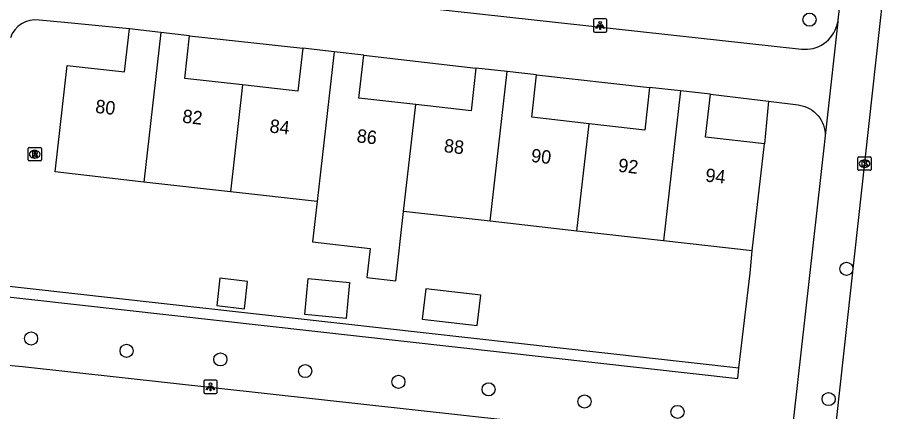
# Model space of a CAD drawing. Extents: x 161928 to 163055, y 386475 to 387428.
# Drawn here: x 162311.1 to 162376.1, y 386864.9 to 386894.3 of the extents above; entities that cross this region are included whole.
import ezdxf

# ---------------------------------------------------------------- set-up
doc = ezdxf.new("R2010")
doc.units = 0
for name, color, linetype in [('IMGEO_Boom', 7, 'Continuous'), ('IMGEO_Groenvoorziening', 7, 'Continuous'), ('IMGEO_Haag', 7, 'Continuous'), ('IMGEO_Kolk', 7, 'Continuous'), ('IMGEO_Lichtpunt', 7, 'Continuous'), ('IMGEO_Pand', 7, 'Continuous'), ('IMGEO_Pand_nummerreeks', 7, 'Continuous'), ('IMGEO_Rijbaan_lokaal_open', 7, 'Continuous'), ('IMGEO_Rioolput', 7, 'Continuous'), ('IMGEO_Voetpad_open', 7, 'Continuous')]:
    doc.layers.add(name, color=color, linetype=linetype)

msp = doc.modelspace()

# ---------------------------------------------------------------- linework, layer by layer
at = {"layer": 'IMGEO_Boom'}
for centre in [(162370.216, 386894.146), (162372.966, 386875.548), (162312.161, 386870.347), (162319.283, 386869.426), (162326.278, 386868.782), (162332.6, 386867.915), (162339.554, 386867.108), (162346.282, 386866.549), (162353.431, 386865.642), (162371.642, 386865.821), (162360.374, 386864.866)]:
    msp.add_circle(centre, 0.489, dxfattribs=at)
at = {"layer": 'IMGEO_Groenvoorziening'}
for points in [[(162367.146, 386888.052), (162366.851, 386884.866)], [(162364.954, 386868.146), (162365.792, 386875.232), (162365.946, 386876.882)]]:
    msp.add_lwpolyline(points, dxfattribs=at)
at = {"layer": 'IMGEO_Haag'}
for points in [[(162308.514, 386874.479), (162364.954, 386868.146)], [(162308.425, 386873.684), (162364.865, 386867.351), (162364.954, 386868.146)]]:
    msp.add_lwpolyline(points, dxfattribs=at)
at = {"layer": 'IMGEO_Kolk'}
for p, q in [((162373.822, 386882.974), (162373.822, 386883.826)), ((162373.897, 386883.9), (162374.749, 386883.9)), ((162374.31, 386883.68), (162374.335, 386883.68)), ((162374.823, 386883.826), (162374.823, 386882.974)), ((162374.749, 386882.9), (162373.897, 386882.9)), ((162374.333, 386883.12), (162374.308, 386883.12))]:
    msp.add_line(p, q, dxfattribs=at)
for points in [[(162373.822, 386882.974), (162373.822, 386883.826)], [(162373.897, 386883.9), (162374.749, 386883.9)], [(162374.143, 386883.6), (162374.266, 386883.6), (162374.266, 386883.449), (162374.396, 386883.6), (162374.56, 386883.6), (162374.414, 386883.449), (162374.567, 386883.2), (162374.415, 386883.2), (162374.33, 386883.364), (162374.266, 386883.297), (162374.266, 386883.2), (162374.143, 386883.2), (162374.143, 386883.6)], [(162374.823, 386883.826), (162374.823, 386882.974)], [(162374.749, 386882.9), (162373.897, 386882.9)]]:
    msp.add_lwpolyline(points, dxfattribs=at)
for centre, start, end in [((162373.899, 386883.824), 91.55205, 178.44795), ((162373.899, 386883.824), 91.55205, 178.44795), ((162374.747, 386883.824), 1.55205, 88.44795), ((162374.747, 386883.824), 1.55205, 88.44795), ((162373.899, 386882.976), 181.55205, 268.44795), ((162373.899, 386882.976), 181.55205, 268.44795), ((162374.747, 386882.976), 271.55205, 358.44795), ((162374.747, 386882.976), 271.55205, 358.44795)]:
    msp.add_arc(centre, 0.0765, start, end, dxfattribs=at)
for centre, major_axis, ratio, start_param, end_param in [((162374.309, 386883.4), (-0.387, 0.002), 0.722429, 4.712389, 7.853982), ((162374.334, 386883.4), (-0.39, 0.002), 0.717154, 1.570796, 4.712389)]:
    msp.add_ellipse(centre, major_axis=major_axis, ratio=ratio, start_param=start_param, end_param=end_param, dxfattribs=at)
at = {"layer": 'IMGEO_Lichtpunt'}
for p, q in [((162354.102, 386894.123), (162354.102, 386893.316)), ((162354.102, 386894.123), (162354.102, 386893.316)), ((162355.004, 386894.218), (162354.196, 386894.218)), ((162355.004, 386894.218), (162354.196, 386894.218)), ((162355.098, 386893.316), (162355.098, 386894.123)), ((162355.098, 386893.316), (162355.098, 386894.123)), ((162354.196, 386893.222), (162355.004, 386893.222)), ((162354.196, 386893.222), (162355.004, 386893.222)), ((162325.037, 386867.135), (162325.037, 386866.328)), ((162325.037, 386867.135), (162325.037, 386866.328)), ((162325.939, 386867.23), (162325.131, 386867.23)), ((162325.939, 386867.23), (162325.131, 386867.23)), ((162326.033, 386866.328), (162326.033, 386867.135)), ((162326.033, 386866.328), (162326.033, 386867.135)), ((162325.131, 386866.234), (162325.939, 386866.234)), ((162325.131, 386866.234), (162325.939, 386866.234))]:
    msp.add_line(p, q, dxfattribs=at)
for points in [[(162354.476, 386893.787), (162354.515, 386893.759), (162354.327, 386893.497), (162354.289, 386893.524), (162354.476, 386893.787)], [(162354.578, 386893.739), (162354.625, 386893.739), (162354.625, 386893.417), (162354.578, 386893.417), (162354.578, 386893.739)], [(162354.688, 386893.759), (162354.726, 386893.786), (162354.913, 386893.524), (162354.874, 386893.496), (162354.688, 386893.759)], [(162325.411, 386866.799), (162325.45, 386866.771), (162325.262, 386866.509), (162325.224, 386866.536), (162325.411, 386866.799)], [(162325.513, 386866.751), (162325.56, 386866.751), (162325.56, 386866.429), (162325.513, 386866.429), (162325.513, 386866.751)], [(162325.623, 386866.771), (162325.661, 386866.798), (162325.848, 386866.536), (162325.809, 386866.508), (162325.623, 386866.771)]]:
    msp.add_lwpolyline(points, dxfattribs=at)
for centre in [(162354.601, 386893.921), (162325.536, 386866.933)]:
    msp.add_circle(centre, 0.0994, dxfattribs=at)
for centre, start, end in [((162354.196, 386894.123), 90, 180), ((162354.196, 386894.123), 90, 180), ((162355.004, 386894.123), 0, 90), ((162355.004, 386894.123), 0, 90), ((162354.196, 386893.316), 180, 270), ((162354.196, 386893.316), 180, 270), ((162355.004, 386893.316), 270, 0), ((162355.004, 386893.316), 270, 360), ((162325.131, 386867.135), 90, 180), ((162325.131, 386867.135), 90, 180), ((162325.939, 386867.135), 0, 90), ((162325.939, 386867.135), 0, 90), ((162325.131, 386866.328), 180, 270), ((162325.131, 386866.328), 180, 270), ((162325.939, 386866.328), 270, 0), ((162325.939, 386866.328), 270, 360)]:
    msp.add_arc(centre, 0.0946, start, end, dxfattribs=at)
at = {"layer": 'IMGEO_Pand'}
for points in [[(162320.569, 386882.025), (162313.947, 386882.776), (162314.848, 386890.729), (162319.14, 386890.243), (162319.504, 386893.456)], [(162321.835, 386893.192), (162319.504, 386893.456)], [(162321.835, 386893.192), (162320.569, 386882.025)], [(162323.976, 386892.949), (162321.835, 386893.192)], [(162327.932, 386889.278), (162323.616, 386889.767), (162323.976, 386892.949)], [(162332.419, 386892.02), (162332.056, 386888.81), (162327.932, 386889.278)], [(162334.756, 386891.755), (162332.419, 386892.02)], [(162334.756, 386891.755), (162333.486, 386880.561)], [(162336.973, 386891.504), (162334.756, 386891.755)], [(162340.85, 386887.811), (162336.609, 386888.292), (162336.973, 386891.504)], [(162345.337, 386890.535), (162344.975, 386887.344), (162340.85, 386887.811)], [(162347.67, 386890.271), (162345.337, 386890.535)], [(162346.403, 386879.097), (162347.67, 386890.271)], [(162349.855, 386890.023), (162347.67, 386890.271)], [(162353.771, 386886.377), (162349.496, 386886.861), (162349.855, 386890.023)], [(162327.932, 386889.278), (162327.027, 386881.293)], [(162358.293, 386889.092), (162357.932, 386885.905), (162353.771, 386886.377)], [(162360.59, 386888.832), (162358.293, 386889.092)], [(162360.59, 386888.832), (162359.32, 386877.633)], [(162362.821, 386888.579), (162360.59, 386888.832)], [(162366.851, 386884.866), (162362.457, 386885.364), (162362.821, 386888.579)], [(162339.945, 386879.829), (162340.85, 386887.811)], [(162352.862, 386878.365), (162353.771, 386886.377)], [(162365.946, 386876.882), (162366.851, 386884.866)], [(162327.027, 386881.293), (162320.569, 386882.025)], [(162333.486, 386880.561), (162327.027, 386881.293)], [(162333.486, 386880.561), (162333.145, 386877.551), (162337.44, 386877.064), (162337.194, 386874.893), (162339.358, 386874.648), (162339.945, 386879.829)], [(162346.403, 386879.097), (162339.945, 386879.829)], [(162352.862, 386878.365), (162346.403, 386879.097)], [(162359.32, 386877.633), (162352.862, 386878.365)], [(162365.946, 386876.882), (162359.32, 386877.633)], [(162328.311, 386874.605), (162326.25, 386874.839), (162326.019, 386872.803), (162328.08, 386872.57), (162328.311, 386874.605)], [(162335.9, 386874.527), (162335.649, 386871.843), (162332.568, 386872.131), (162332.819, 386874.815), (162335.9, 386874.527)], [(162345.693, 386873.589), (162341.595, 386874.053), (162341.337, 386871.778), (162345.435, 386871.314), (162345.693, 386873.589)]]:
    msp.add_lwpolyline(points, dxfattribs=at)
at = {"layer": 'IMGEO_Rijbaan_lokaal_open'}
msp.add_lwpolyline([(162371.672, 386859.36), (162371.777, 386860.229), (162372.249, 386864.452), (162381.298, 386946.838), (162381.805, 386950.758), (162381.864, 386951.24)], dxfattribs=at)
at = {"layer": 'IMGEO_Rioolput'}
for p, q in [((162312.01, 386884.6), (162312.862, 386884.6)), ((162311.935, 386883.674), (162311.935, 386884.526)), ((162312.423, 386884.38), (162312.448, 386884.38)), ((162312.936, 386884.526), (162312.936, 386883.674)), ((162312.862, 386883.6), (162312.01, 386883.6)), ((162312.446, 386883.82), (162312.421, 386883.82))]:
    msp.add_line(p, q, dxfattribs=at)
for points in [[(162312.01, 386884.6), (162312.862, 386884.6)], [(162311.935, 386883.674), (162311.935, 386884.526)], [(162312.524, 386884.298), (162312.272, 386884.3), (162312.272, 386883.9)], [(162312.272, 386883.9), (162312.396, 386883.9), (162312.396, 386884.062), (162312.407, 386884.062)], [(162312.45, 386884.219), (162312.396, 386884.219), (162312.396, 386884.138)], [(162312.396, 386884.138), (162312.448, 386884.138)], [(162312.454, 386884.033), (162312.525, 386883.9), (162312.665, 386883.9), (162312.6, 386884.026)], [(162312.936, 386884.526), (162312.936, 386883.674)], [(162312.862, 386883.6), (162312.01, 386883.6)]]:
    msp.add_lwpolyline(points, dxfattribs=at)
for centre, radius, start, end in [((162312.012, 386884.524), 0.0765, 91.55205, 178.44795), ((162312.012, 386884.524), 0.0765, 91.55205, 178.44795), ((162312.86, 386884.524), 0.0765, 1.55205, 88.44795), ((162312.86, 386884.524), 0.0765, 1.55205, 88.44795), ((162312.406, 386884.009), 0.0533, 26.02933, 88.69889), ((162312.432, 386884.327), 0.19, 274.7715, 282.96867), ((162312.456, 386884.123), 0.0964, 77.00612, 93.18647), ((162312.47, 386884.18), 0.0378, 276.66336, 79.67722), ((162312.523, 386884.188), 0.109, 350.36119, 89.41601), ((162312.521, 386884.188), 0.112, 277.58423, 350.98172), ((162312.505, 386883.973), 0.108, 29.51342, 73.79051), ((162312.012, 386883.676), 0.0765, 181.55205, 268.44795), ((162312.012, 386883.676), 0.0765, 181.55205, 268.44795), ((162312.86, 386883.676), 0.0765, 271.55205, 358.44795), ((162312.86, 386883.676), 0.0765, 271.55205, 358.44795)]:
    msp.add_arc(centre, radius, start, end, dxfattribs=at)
for centre, major_axis, ratio, start_param, end_param in [((162312.422, 386884.1), (-0.387, 0.002), 0.722429, 4.712389, 7.853982), ((162312.447, 386884.1), (-0.39, 0.002), 0.717154, 1.570796, 4.712389)]:
    msp.add_ellipse(centre, major_axis=major_axis, ratio=ratio, start_param=start_param, end_param=end_param, dxfattribs=at)
at = {"layer": 'IMGEO_Voetpad_open'}
for points in [[(162374.683, 386914.918), (162372.335, 386894.112), (162372.318, 386893.989)], [(162313.257, 386898.144), (162315.471, 386897.91), (162369.622, 386891.948), (162369.841, 386891.933), (162370.06, 386891.938), (162370.278, 386891.962), (162370.493, 386892.006), (162370.703, 386892.069), (162370.907, 386892.15), (162371.103, 386892.249), (162371.289, 386892.365), (162371.464, 386892.498), (162371.626, 386892.645), (162371.775, 386892.807), (162371.908, 386892.981), (162372.026, 386893.166), (162372.126, 386893.361), (162372.209, 386893.564), (162372.273, 386893.774), (162372.318, 386893.989)], [(162319.504, 386893.456), (162314.661, 386893.924), (162312.752, 386894.12)], [(162372.318, 386893.989), (162371.364, 386885.262)], [(162323.976, 386892.949), (162332.419, 386892.02)], [(162336.973, 386891.504), (162345.337, 386890.535)], [(162349.855, 386890.023), (162358.293, 386889.092)], [(162362.821, 386888.579), (162367.146, 386888.052)], [(162367.146, 386888.052), (162369.374, 386887.78), (162369.465, 386887.767), (162369.664, 386887.725), (162369.859, 386887.666), (162370.048, 386887.589), (162370.23, 386887.496), (162370.402, 386887.387), (162370.564, 386887.263), (162370.714, 386887.125), (162370.851, 386886.974), (162370.975, 386886.811), (162371.083, 386886.639), (162371.175, 386886.457), (162371.251, 386886.267), (162371.309, 386886.072), (162371.35, 386885.872), (162371.373, 386885.669), (162371.378, 386885.465), (162371.364, 386885.262)], [(162371.364, 386885.262), (162369.017, 386864.388), (162369.001, 386864.271)], [(162369.001, 386864.271), (162368.956, 386864.053), (162368.892, 386863.841), (162368.808, 386863.634), (162368.707, 386863.436), (162368.589, 386863.248), (162368.454, 386863.071), (162368.304, 386862.907), (162368.14, 386862.757), (162367.963, 386862.622), (162367.774, 386862.504), (162367.576, 386862.403), (162367.37, 386862.32), (162367.157, 386862.255), (162366.939, 386862.211), (162366.718, 386862.185), (162366.496, 386862.18), (162366.274, 386862.194), (162311.525, 386868.224), (162309.911, 386868.373)]]:
    msp.add_lwpolyline(points, dxfattribs=at)
msp.add_arc((162312.488, 386892.158), 1.98, 82.33642, 161.20099, dxfattribs=at)

# ---------------------------------------------------------------- texts
at = {"layer": 'IMGEO_Pand_nummerreeks'}
for s, rotation, p in [('80', 353.56744, (162316.912, 386887.196)), ('82', 353.56744, (162323.407, 386886.463)), ('84', 353.56744, (162329.91, 386885.73)), ('86', 353.56568, (162336.41, 386884.997)), ('88', 353.56744, (162342.914, 386884.264)), ('90', 353.56744, (162349.414, 386883.531)), ('92', 353.56744, (162355.909, 386882.799)), ('94', 353.56744, (162362.412, 386882.066))]:
    msp.add_text(s, height=1, rotation=rotation, dxfattribs=at).set_placement(p)

doc.saveas('drawing.dxf')
